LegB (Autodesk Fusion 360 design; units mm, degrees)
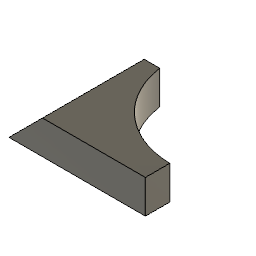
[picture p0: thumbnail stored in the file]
sketch "Sketch2" plane through (0, 0, 0) normal (0, 0, 1) x axis (1, 0, 0)
  line L1 (34.0614, 1.7525) -> (0, 1.7525)
  line L2 (34.0614, 7.8862) -> (34.0614, 1.7525)
  line L3 (0, 27.1525) -> (12.2674, 27.1525)
  line L4 (0, 1.7525) -> (0, 27.1525)
  arc A1 centre (34.4882, 30.3289) radius 22.4467 clockwise from (34.0614, 7.8862) to (12.2674, 27.1525)
  point P2 (0, 1.7525)
  point P3 (34.0614, 1.7525)
  point P4 (0, 27.1525)
  horizontal L1
  vertical L2
  horizontal L3
  vertical L4
  dimension "d1" distance P2 P3 = 34.0614
  dimension "d2" distance P2 P4 = 25.4
extrude "Extrude1" new body sketch "Sketch2" along normal blind 8.382
sketch "Sketch3" plane through (0, 27.1525, 0) normal (0, 1, 0) x axis (-1, 0, 0)
  line L1 (0, 0) -> (-12.2674, 0)
  line L2 (0, 8.382) -> (0, 0)
  line L3 (-12.2674, 8.382) -> (0, 8.382)
  line L4 (-12.2674, 0) -> (-12.2674, 8.382)
  line L5 (-8.382, 8.382) -> (0, 8.382)
  line L6 (0, 8.382) -> (0, 0)
  line L7 (-8.382, 8.382) -> (0, 0)
  point P4 (0, 8.382)
  point P6 (0, 8.382)
  point P3 (0, 0)
  point P9 (0, 0)
  point P7 (-8.382, 8.382)
  point P8 (0, 0)
  horizontal L5
  vertical L6
  coincident P4 P6
  coincident P3 P9
  dimension "d5" distance P6 P7 = 8.382
  dimension "d6" distance P6 P8 = 8.382
split "Split1"
remove_body "RemoveBody1"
